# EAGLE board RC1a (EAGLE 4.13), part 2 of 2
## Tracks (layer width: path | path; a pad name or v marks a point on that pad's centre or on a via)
19GHZANT  (via drill 0.7, 3.2 pad 5.84)
  Top 0.305: 102.78,78.88 102.66,79.01 | 102.78,78.88 102.78,78.76 103.93,78.76 | 102.78,78.88 v101.64,78.88
  Top 2.54: v103.93,49.04 v103.93,56.4 v103.93,63.77 v103.93,72.28 103.93,78.76
  Bottom 2.54: v103.93,49.04 v103.93,56.4 v103.93,63.77 v103.93,72.28 103.93,78.12 103.67,78.88 v101.64,78.88
19GHZANT1  (via drill 0.7, 3.2 pad 6.45)
  Top 0.305: 155.98,78.9 155.86,79.02 | 155.98,78.9 155.98,78.77 156.87,78.64 | v154.84,78.9 155.98,78.9
  Top 2.54: v156.87,55.27 v156.87,63.78 v156.87,72.29 156.87,78.64
  Bottom 2.54: v156.87,55.27 v156.87,63.78 v156.87,72.29 156.87,78.9 v154.84,78.9
19GHZANT2  (via drill 0.7, 3.2 pad 6.45)
  Top 0.305: 48.29,79.53 48.16,79.66 | 48.29,79.53 48.29,79.4 49.43,79.4 | 48.29,79.53 v48.16,79.28
  Top 2.54: v49.43,50.45 v49.43,57.05 v49.43,64.42 v49.43,72.93 49.43,79.4
  Bottom 2.54: v49.43,50.45 v49.43,57.05 v49.43,64.42 v49.43,72.93 49.43,78.77 49.18,79.53 v48.16,79.28
800MHZANT  (via drill 0.7, 3.2 pad 5.84)
  Top 0.305: 56.56,79.01 57.19,79.64 v58.46,78.88
  Top 0.406: 56.43,73.8 56.18,73.55 56.56,73.17 v56.56,69.74
  Top 2.54: 56.43,21.99 v56.56,22.24 v56.56,31.77 v56.56,41.42 v56.56,51.45 v56.56,60.21 v56.56,69.74 56.56,79.01
  Bottom 2.54: v58.46,78.88 56.81,78.88 56.43,78.12 56.43,21.86
800MHZANT1  (via drill 0.7, 3.2 pad 6.45)
  Top 0.305: 109.76,79.02 110.39,79.66 v111.66,78.9
  Top 0.406: 109.63,73.82 109.38,73.56 109.76,73.18
  Top 2.54: 109.76,21.24 v109.76,21.36 v109.76,29.24 v109.76,37.75 109.76,42.19 | 109.76,42.57 v109.76,52.61 v109.76,61.12 v109.76,70.26 109.76,73.18 109.76,79.02 | 109.76,42.19 v109.76,45.11 109.76,42.57 | 109.76,42.19 109.76,42.57
  Bottom 2.54: v111.66,78.9 110.01,78.9 109.63,78.13 109.63,20.98
800MHZANT2  (via drill 0.7, 3.2 pad 6.45)
  Top 0.305: 2.82,79.66 3.46,80.29 v4.98,79.28
  Top 0.406: v2.7,74.45 2.44,74.2 2.82,73.82 2.82,70.39
  Top 2.54: 2.82,11.08 v2.82,11.33 v2.82,17.43 v2.82,24.29 v2.82,31.52 v2.82,39.65 v2.82,47.78 v2.82,56.8 v2.82,65.69 2.82,70.39 2.82,79.66
  Bottom 2.54: v4.98,79.28 3.08,79.53 2.7,78.77 2.82,10.95
+6V  (via drill 0.5, 0.6)
  Top 0.305: 196.88,30.89 v196.88,32.67 | 202.85,28.86 203.23,28.73 203.1,28.61 C56.1 | 203.1,25.43 203.23,25.56 203.1,25.66 C15.1 | 203.04,23.08 202.97,23.02 C54.1
  Top 0.406: 196.88,30.89 202.85,30.89 202.85,28.86 202.85,26.19 | 202.85,26.19 203.1,25.43 203.1,23.27 203.04,23.08 203.1,23.02 | 203.37,25.92 203.36,25.81 202.85,26.19 | C54.1 205.14,23.15 205.26,23.27 205.25,23.28 R8.2 208.3,23.28 208.31,23.27 208.4,23.36 C26.+ 208.55,20.24 208.56,20.98 208.55,20.97 D2.C 210.31,19.62 211.1,18.82 211.1,12.73 208.31,12.73 207.29,11.71 v207.29,8.92 | C14.1 184.31,20.48 | C14.1 | 183.78,19.7 183.78,19.95 C14.1
  Top 0.508: v190.64,13.1 188.37,15.9 185.55,15.9 183.78,17.67 183.78,19.7 | IC11.7 187.08,57.93 190.51,57.93 v190.51,51.96
  Top 0.61: C14.1 | C14.1 184.8,20.97 | C14.1 184.04,20.21
  Bottom 0.305: 190.64,51.58 190.64,51.83 190.53,51.95 | 190.53,51.95 v190.51,51.96 | 190.53,51.95 190.53,38.38 193.58,35.33 196.37,35.33 196.88,34.83 v196.88,32.67
  Bottom 0.406: v190.51,51.96 190.77,51.96 | 201.7,9.81 201.7,7.1 R19.1 201.6,6.61 201.58,6.63 201.83,6.89 | 201.7,9.81 201.96,10.19 195.1,10.19 194.47,10.95 | 194.47,10.95 194.47,12.47 193.83,13.11 191.9,13.11 v190.64,13.1 | 192.83,8.02 192.95,7.89 | 192.83,8.02 C37.1 | 192.95,7.89 IC8.8 | 192.95,7.89 193.07,7.78 | 192.83,8.02 194.47,9.65 194.47,10.95 | v207.29,8.92 207.29,9.05 205.26,9.05 204.12,10.19 202.09,10.19 201.7,9.81
+12V  (via drill 0.5)
  Top 0.305: IC12.3 186.87,49.17 v185.94,49.04
  Top 0.406: 186.7,32.95 D3.C 186.11,32.83 184.94,31.65 183.8,31.65 | 183.02,28.85 183.15,28.72 183.15,28.47 | 183.15,28.47 183.15,28.34 | 183.15,28.47 183.02,28.47 | C19.1 183.28,28.47 183.15,28.47 | 183.29,28.34 183.29,28.35 | C19.1 183.29,28.34 | 183.29,28.34 183.29,28.22 | v181.26,36.35 181.26,34.57 181.28,32.67 181.38,32.56 | C19.1 183.29,28.45 | 181.38,32.56 181.38,32.41 182.15,31.65 183.8,31.65 | C27.+ 181.38,33.11 181.38,32.56 | C19.1 183.42,28.35 183.42,31.27 183.8,31.65
  Top 0.61: IC4.4 189.88,33.55 189.16,32.83 D3.C
  Bottom 0.61: 185.19,49.56 168.18,49.56 168.18,51.21 161.57,51.21 161.57,39.53 163.94,39.53 IC13.3 163.94,39.73 163.86,39.65 163.86,37.62 165.13,36.35 v181.26,36.35
  Bottom 0.813: 185.19,49.56 185.81,48.94 v185.94,49.04
+24V  (via drill 0.5)
  Top 0.305: C18.1 167.8,21.5 167.67,21.63 | v167.41,23.02 167.67,23.12 R13.2 | 181.51,0.92 181.64,0.79 185.45,0.79
  Top 0.406: v188.1,12.85 184.56,9.18 | 172.89,1.29 167.41,6.89 v167.41,12.22 | R13.2 169.03,25.01 168.9,25.14 | C18.1 168.32,20.87 | 167.8,21.5 167.8,21.49 167.41,21.87 v167.41,23.02 | 167.8,21.5 | 168.9,25.14 166.58,27.46 164.29,27.46 C20.+ 164.24,27.51 | 164.24,27.51 164.24,27.33 | C55.1 164.24,30.26 164.24,27.51 | 168.9,25.14 168.81,25.05 168.81,26.65 D4.C
  Top 0.508: 172.89,1.29 173.26,0.92 181.51,0.92 | 185.45,0.79 187.73,0.79 187.73,4.09 184.56,7.27 184.56,9.18
  Bottom 0.305: IC9.8 194.79,13.42 192.81,14.89 188.1,14.89 188.37,15.4 188.61,15.63 C35.1
  Bottom 0.406: 188.1,14.89 v188.1,12.85 | v167.41,12.22 v167.41,23.02
CLK
  Bottom 0.254: 186.08,24.16 180.62,29.62 172.11,29.62 IC14.9
  Bottom 0.305: IC6.24 190.06,24.16 186.08,24.16
CP_IF  (via drill 0.5)
  Top 0.305: R40.2 183.15,55.01 183.15,52.34 182.51,51.71 182.53,37.37 178.72,37.37 | v178.72,33.68 178.72,37.37 | 178.72,37.37 178.72,36.1 C83.1
  Top 0.406: 183.15,55.01 183.53,55.39 v183.53,56.28
  Bottom 0.305: IC16.5 183.54,56.29 v183.53,56.28 | IC6.28 186.08,27.84 181.13,32.79 178.84,32.79 179.36,32.66 R41.1 178.84,32.67 178.72,32.67 v178.72,33.68
CP_RF  (via drill 0.5)
  Top 0.254: 184.93,53.23 184.93,56.66
  Top 0.305: v188.23,56.66 184.93,56.66 184.8,56.66 183.91,57.55 182.89,57.55 | 182.89,57.55 182.89,57.42 | 184.93,53.23 183.15,51.45 183.15,36.75 v183.8,36.1 | 182.89,57.55 R42.2
  Bottom 0.254: 190.53,30.79 189.26,32.06 189.26,34.19
  Bottom 0.305: IC16.13 189.42,58.24 188.23,57.04 v188.23,56.66 | IC6.23 191.07,23.05 190.78,22.76 189,22.76 188.26,22.78 R43.2 186.85,22.76 186.85,21.62 C84.1 | 189.26,34.19 187.35,36.1 v183.8,36.1
  Bottom 0.406: IC6.23 191.07,30.22 190.53,30.79
D+
  Top 0.305: U$6.3 83.16,7.95 83.61,7.51 83.61,2.43 82.46,1.29 76.37,1.29 76.15,1.51 IC2.15
D+1
  Top 0.305: U$1.2 135.56,7.88 136.05,7.39 136.05,4.22 133.34,1.52 131,1.52 130.33,2.19 129.31,2.19 IC3.16
D-
  Top 0.305: IC2.16 76.11,2.17 77.13,2.17 77.38,1.92 82.21,1.92 82.97,2.68 82.97,7.25 82.34,7.89 82.34,8.91 82.36,8.93 U$6.2
D-1
  Top 0.305: U$1.3 136.36,7.97 136.81,7.52 136.81,3.97 133.76,0.92 129.82,0.92 129.31,1.43 129.33,1.44 IC3.15
FB
  Top 0.305: IC5.8 174.27,17.68 172.62,17.68 | R14.2 171.07,17.68 172.62,17.68 | R13.1 172.62,22.41 172.62,17.68
GND  (via drill 0.6)
  Top 0.305: IC1.2 100.24,14.75 100.88,14.11 102.66,14.11 102.66,15.83 | 102.66,15.83 102.66,15.89 | IC1.4 102.66,15.83 | R2.1 66.34,3.89 66.78,3.89 66.84,4.21 66.84,8.4 66.34,8.91 66.34,11.32 66.97,11.95 70.27,11.95 | 70.27,11.95 C7.2 70.02,11.95 70.02,13.35 74.71,13.35 | 70.27,11.95 70.4,11.95 | 74.72,13.35 74.84,13.35 74.84,12.21 C6.2 74.71,13.35 | C1.- 80.15,13.35 74.72,13.35 | 74.72,13.35 74.71,13.35
  Top 0.406: R1.1 101.77,10.31 103.67,12.33 | 103.67,12.33 C3.2 | IC1.4 103.67,14.94 103.67,12.33 | C1.- 80.56,13.6
  Top 0.61: C1.- 80.31,13.6 80.31,12.33 v80.56,12.08 | 100.5,9.29 98.47,7.25 93.06,7.25 91.21,9.1 91.21,9.19 | R1.1 101.77,9.29 100.5,9.29 | 100.5,9.29 v99.36,10.43 | 91.21,9.19 91.21,9.29 | 91.21,9.19 J1.RING
  Bottom 0.61: v80.56,12.08 80.69,12.21 97.56,12.21 97.58,12.22 97.58,12.21 v99.36,10.43
GND1  (via drill 3.2 pad 6.45)
  Top 0.305: 123.22,13.36 127.91,13.36 | C10.2 123.22,11.96 123.22,13.36 | 127.91,13.36 C12.2 128.04,12.22 128.04,13.36 127.91,13.36 | 129.33,8.16 IC3.25 127.66,8.02 127.66,5.36 | 129.33,8.16 IC3.26 127.53,8.67 127.53,8.66 | 129.33,8.16 129.31,8.16 | 127.66,5.42 IC3.21 | 127.66,5.42 124.49,5.42 124.49,6.07 IC3.7 | IC3.18 127.66,3.47 127.66,5.36 | 127.66,5.36 127.66,5.42 | 127.53,8.66 127.54,8.66 | 127.28,11.21 127.28,8.66 127.53,8.66 | 139.22,13.36 123.22,13.36
  Top 0.406: U$1.5 137.95,9.08 137.95,9.68 139.22,10.95 139.22,13.36 139.22,16.34 C11.- | C12.2 127.28,11.21
  Top 0.813: JP1.4 111.53,17.68 113.95,15.27 C8.2 114.22,15.25 114.33,15.14 114.34,15.15 C9.2 117.17,25.23 119.54,27.59 131.35,27.59 134.39,24.54 BAT2.- 139.42,19.38 C11.-
  Top 1.27: v156.11,3.97 153.32,3.97 141,16.28 139.6,16.28 139.42,16.46 C11.-
GND2  (via drill 0.5, 0.6, 1.6, 2, 3.2 pad 5.84)
  Top 0.254: IC4.8 193.56,26.69 | 207.67,38.64 208.44,38.51 209.58,38.51
  Top 0.305: 176.7,38.27 v178.32,39.9 178.32,40.15 | IC4.8 193.69,26.69 | VCO2.P$1 171.46,39.77 | 191.05,33.57 191.15,33.67 | 191.05,33.57 IC4.3 191.16,33.59 | 191.05,33.57 191.02,33.55 | 195.34,39.64 VCO1.P$1 v195.09,39.77 | 181.88,44.21 181.62,44.47 181.62,41.17 | U$8.GND4 178.19,79.39 | v185.69,40.79 185.31,40.4 | 177.46,38.12 176.8,38.12 176.67,38.25 176.68,38.25 | 170.84,20.98 | 170.84,20.98 R14.1 | C18.2 170.84,20.5 170.84,20.98 | C28.2 176.56,15.4 176.56,12.56 177.54,11.59 | IC4.8 193.69,26.97 193.7,26.95 v193.58,26.83 | C14.2 184.31,23.27 184.43,23.14 v184.18,23.27 | IC4.1 193.7,32.16 v192.48,31.04 | 178.34,21.49 178.46,21.62 v178.21,21.62 | 208.31,38.76 207.67,38.64 207.8,35.74 JP4.6 | 176.68,38.25 176.69,38.26 | v174.65,33.18 174.65,36.1 | 174.65,36.1 174.65,38.26 176.68,38.25 | C15.2 205.26,25.93 205.26,28.47 C56.2 | C57.2 200.31,3.97 202.85,3.97 202.85,1.55 202.97,1.55 R32.2 | IC4.8 193.7,27.44 193.7,27.59 197.26,27.59 C58.2 | 174.65,36.1 C83.2
  Top 0.406: 193.82,27.55 IC4.8 193.71,27.45 193.82,27.45 | 191.15,33.67 191.28,33.8 | 171.21,39.64 171.21,39.77 VCO2.P$1 | IC10.2 174.38,5.23 172.48,5.23 171.72,5.99 171.72,6.75 171.84,7.26 | 171.84,7.26 171.78,7.32 | 171.78,7.32 171.85,7.38 | 171.75,11.2 171.84,7.26 | 171.72,12.72 171.75,11.2 | 171.72,12.72 169.05,15.39 C25.- 169.19,15.1 169.19,15.14 165.89,15.14 163.48,17.55 | v188.74,39.26 188.74,38.5 | 171.78,7.32 171.72,7.38 171.59,7.38 C21.2 | 182.89,23.26 C14.2 | 182.89,23.26 182.89,25.55 C19.2 183.54,25.68 183.67,25.68 | 182.91,23.4 182.91,17.17 183.54,16.54 v183.54,13.24 183.48,13.3 184.18,14.25 188.37,14.25 189.26,13.36 v189.26,11.08 | 182.91,23.4 182.91,23.65 | 182.89,23.26 183.04,23.37 182.91,23.4 | 171.75,11.2 171.86,11.2 | 177.54,11.59 C24.- 178.94,9.81 178.59,10.16 v178.59,11.33 | 171.72,12.72 171.73,12.73 v171.73,15.78 173.1,15.78 C16.2 173.51,16.19 173.51,16.16 175.67,16.16 C28.2 176.56,15.27 | IC5.4 180.42,21.49 178.34,21.49 178.08,21.75 | IC5.7 174.4,19.08 176.18,19.08 | 176.18,19.08 176.18,21.49 174.27,21.49 | 174.27,21.49 | 174.27,21.49 IC5.5 | 176.56,15.27 176.56,15.14 | 176.18,19.08 176.56,18.7 176.56,15.4 176.56,15.27 | 163.48,17.55 JP2.4 164.16,18.36 C20.- 164.05,20.6 163.99,20.6 163.99,22.51 161.83,24.67 161.83,31.02 163.35,32.54 165.64,32.54 | C18.2 167.9,17.55 163.48,17.55 | v193.43,10.56 193.58,10.56 193.58,15.26 195.52,15.26 195.72,15.39 195.72,15.64 195.75,15.16 R7.1 195.86,15.4 195.74,15.91 198.65,18.82 198.66,19.33 198.66,23.9 198.28,24.41 C58.2 | v177.69,68.09 177.44,67.96 177.45,67.97 Q5.2 | v209.45,3.84 209.32,3.84 207.03,1.54 R32.2 | v209.96,17.3 208.18,17.3 207.8,17.68 IC17.2
  Top 0.406: R9.1 201.46,23.66 v201.7,23.78 | v210.34,29.75 210.33,29.76 C26.- 208.93,28.49 208.94,28.73 208.96,25.82 C15.2 | C17.2 179.86,4.72 179.86,6 v179.23,6.63 | C55.2 167.54,32.54 165.64,32.54 | C27.- 176.05,32.95 176.05,32.79 175.8,33.05 174.65,33.05 v174.65,33.18 | IC4.3 191.15,34.94 191.67,35.46 193.45,35.46 193.7,35.21 193.7,33.56 IC4.1 | IC4.1 | 165.64,32.54 165.11,33.06 | C13.2 200.31,3.97
  Top 0.61: 183.15,23.39 C14.2 | 201.07,68.86 Q4.2 | 165.11,33.06 v165.11,38.12
  Top 1.27: Q4.2 196.88,68.86 | Q5.2 173.38,67.97
  Bottom 0.254: IC16.14 192.16,57.59 192.42,57.84 192.42,58.69 192.16,58.95 191.11,58.95 IC16.12 191.02,58.89 | v193.58,26.83 192.67,25.53 | 193.58,27.59 193.7,27.46 193.7,26.95 | 191.87,31.27 192.12,31.02 v192.48,31.04 | 210.09,25.17 209.98,24.84 | 201.86,24.84 201.7,24.67 v201.7,23.78
  Bottom 0.305: D6.A 178.32,40.15 v178.32,39.9 | U$8.GND4 178.07,80.54 v177.69,78 | v173.37,78.12 U$8.GND | U$9.GND4 201.82,79.65 201.94,79.77 200.93,77.74 | 183.27,60.6 C73.2 183.15,60.69 | C72.2 181.92,60.6 183.27,60.6 | C71.2 195.17,52.89 195.21,52.85 C70.2 196.61,52.89 196.61,52.6 | v183.02,80.16 183.27,80.79 183.4,75.97 | v192.42,78.63 190.39,77.23 191.02,76.6 C81.2 | 183.27,60.6 179.59,60.6 179.21,60.98 179.21,70.88 180.86,74.31 183.53,74.31 183.66,74.44 | 196.61,52.22 v196.61,52.47 196.61,52.6 | 196.61,56.28 C80.2 | 196.61,52.6 196.61,56.28 | 192.42,57.84 192.42,58.95 196.99,58.95 196.99,56.28 196.61,56.28 | 187.59,47.43 C76.2 | C77.2 187.59,48.75 187.59,47.43 | v185.69,40.79 185.94,41.42 IC15.2 185.94,45.9 C39.2 186.58,46.5 187.5,47.43 187.59,47.43 | IC16.2 183.87,54.34 183.27,53.74 182.13,53.74 C74.2 | C75.2 180.65,53.7 180.48,53.87 v179.97,53.87 | 178.36,18.72 178.46,18.82 IC14.1 178.46,19.46 178.34,19.33 178.19,19.48 177.3,19.48 177.19,19.59 IC14.2 177.19,19.46 177.45,19.71 177.45,20.73 | 173.38,19.46 173.38,17.3 171.61,15.52 | IC9.4 202.21,18.64 202.21,20.51 R20.1 201.7,21.52 v201.7,23.78 201.58,23.65 | C37.2 192.69,10.7 192.69,10.57 | 209.58,11.33 209.59,11.35 R22.1 | 209.58,11.33 209.47,11.44 | C23.2 209.44,16.79 209.45,16.79 209.47,16.78 | C23.2 209.44,16.55 209.45,16.54 209.47,16.56 | 209.83,18.32 209.58,18.32 209.44,18.18 | 177.45,20.73 176.81,21.36 173.89,21.36 173.38,20.86 173.38,19.46 | 173.38,19.46 IC14.5 | 191.54,20.98 191.54,21.24 192.69,22.38 192.69,23.97 | 191.54,20.98 191.54,20.76 C30.2 191.53,21 191.54,20.98 | 192.69,23.97 192.69,24.16 | 192.69,23.97 IC6.21 192.67,25.53
  Bottom 0.305: C35.2 189.01,18.56 190.53,17.05 192.81,17.05 192.81,19.71 191.54,20.98 | v184.18,23.27 184.14,22.67 R43.1 184.03,22.76 184.18,22.76 184.18,21.75 C84.2 | 191.87,31.27 IC6.3 | IC6.5 193.45,32.29 193.45,31.65 192.81,31.02 v192.48,31.04 191.93,30.38 191.93,29.11 193.58,27.59 | 193.7,26.83 v193.58,26.83 193.7,26.95 | 177.45,20.73 178.46,21.75 | 178.46,21.75 IC14.14 | 178.46,21.75 178.34,21.62 v178.21,21.62 | 209.83,38.26 209.7,38.39 | 209.58,11.33 209.71,11.2 210.47,11.2 | 210.47,15.27 210.21,15.27 210.21,15.28 | 210.21,15.28 C23.2 | 210.09,14.89 210.21,14.89 210.21,15.28 | 209.96,18.44 209.83,18.57 209.83,18.85 C22.2 | 210.59,21.75 210.47,21.75 209.73,21.75 R15.2 | 209.98,24.84 201.86,24.84 | R41.2 176.01,32.96 v174.65,33.18 | D5.A 193.03,6.63 188.62,6.63 188.37,6.89 188.37,10.7 188.62,10.95 189.26,10.95 v189.26,11.08
  Bottom 0.406: C38.2 v188.74,39.26 | 162.83,17.93 162.83,17.8 JP2.4 | 178.46,9.88 178.46,9.93 | 178.46,9.88 IC7.1 178.46,9.85 178.46,9.55 | 178.46,9.55 178.46,8.41 | 178.21,6.76 C29.2 178.46,7.24 | R11.1 178.21,4.47 178.21,6.76 | 178.21,6.76 178.21,6.89 177.96,6.63 v179.23,6.63 | C32.2 171.61,14.61 171.61,15.52 171.61,15.65 v171.73,15.78 | 178.46,7.24 178.46,7.14 | 178.46,7.24 178.46,9.55 | 178.46,9.55 178.46,9.88 | IC8.6 190.33,10.57 190.4,10.57 190.4,11.08 | 190.4,11.49 IC8.5 190.31,11.59 | 190.4,11.08 190.4,11.49 | IC8.4 184.22,12.47 v183.54,13.24 | 192.43,11.33 192.56,11.33 | 192.43,11.33 192.28,11.33 | C37.2 193.05,10.57 | 209.07,4.09 209.32,3.84 v209.45,3.84 | 210.47,25.3 210.09,25.17 | 210.34,25.3 210.34,24.92 | 210.34,24.92 210.34,25.17 | 210.09,25.17 210.34,24.92 | 210.09,25.17 210.47,24.79 210.47,25.68 | v178.59,11.33 178.46,11.2 178.46,9.55 | C37.2 192.69,10.82 192.69,11.49 | 190.4,11.49 192.69,11.49 | 192.43,11.33 192.43,11.2 | 192.69,11.49 192.43,11.49 192.43,11.33 | C37.2 192.94,10.82 192.94,10.56 v193.43,10.56 | v189.26,11.08 190.4,11.08 | 209.96,14.76 210.09,14.63 | 210.09,14.89 209.96,14.76 | 209.96,14.76 209.83,14.76 | R16.2 209.47,14.27 209.96,14.76 | 209.96,18.44 v209.96,17.3 | 210.47,29.62 v210.34,29.75
  Bottom 0.508: 162.83,17.8 162.71,17.8
  Bottom 0.813: 209.71,3.97 209.58,3.84 v209.45,3.84 207.16,1.54 197.52,1.54 194.47,4.6 194.34,4.6 194.67,4.93 D5.A
  Bottom 1.27: v209.45,3.84 209.83,5.11 210.47,5.74 210.47,11.2 210.47,15.27 210.47,17.17 209.83,18.32 209.96,18.44 210.47,18.95 210.47,21.75 210.47,24.79 210.47,25.3 210.34,25.3 210.47,25.68 210.47,29.62 210.47,37.62 209.83,38.26 209.83,39.27 206.53,39.4 206.53,39.28 v206.52,41.42
  other vias: 189.5,78.89 204.1,41.55 201.82,39.77 202.83,42.06 200.42,41.93 203.98,44.47 203.98,47.9 201.18,48.66 202.32,50.69 197.24,50.44 194.96,50.44 198.01,48.79 198.64,45.74 201.56,44.98 198.39,42.94 196.1,42.94 195.8,45.36 195.59,47.77 211.88,40.56 194.96,42.06 204.86,64.53 184.54,81.81 181.12,70.12 166.13,54.76 203.98,78 203.72,80.16 196.86,60.72 194.32,81.04 190.77,81.3 196.86,62.38 185.31,78.5 204.1,51.45 181.12,47.9 176.92,47.9 173.04,47.82 179.39,45.36 176.04,39.13 174.51,43.83 171.72,45.33 176.04,41.8 169.3,45.23 175.02,47.9 177.97,43.4 171.72,42.61 178.96,47.9 169.43,41.8 171.08,47.9 180.86,40.91 171.59,69.74 171.08,76.98 180.35,79.65 162.32,66.82 173.5,51.33 177.69,51.45 171.59,51.33 162.19,52.6 163.21,74.69 165.11,74.31 167.15,74.19 169.05,72.79 170.96,81.04 162.19,71.14 181.42,44.16 210.07,41.55 206.52,43.71 169.69,51.33 163.08,48.02 188.61,70 179.21,64.41 179.72,59.33 168.92,81.55 169.05,54.88 171.21,60.85 168.92,58.82 166.76,57.55 165.11,62.88 168.54,61.87 165.11,66.44 206.64,47.9 209.94,45.74 210.33,50.18 206.64,52.09 210.71,54.5 206.64,59.33 211.72,75.33 207.79,70.88 211.6,64.92 205.25,81.68 207.91,64.92 203.85,61.11 209.06,61.61 207.91,55.77 211.09,58.69 161.68,76.47 172.86,76.6 169.56,77.62 169.56,64.28 173.37,79.9 177.69,79.65 177.69,81.43 173.24,81.68 180.35,65.8 179.85,74.31 179.46,61.61 181.24,60.47 196.86,65.8 192.8,66.69 196.86,64.03 196.86,59.07 185.94,43.71 197.12,79.39 197.12,81.17 194.07,76.6 187.08,64.53 200.93,79.77 201.05,81.55 171.46,57.17 172.99,53.87 173.11,55.39 172.99,58.82 173.11,60.6 172.99,62.38 177.69,58.57 177.69,53.74 177.69,55.39 177.69,60.6 177.69,62.5 172.86,64.03 172.99,66.31 172.99,67.96 172.99,69.74 175.91,67.96 174.26,67.96 171.72,72.28 171.08,79.01 181.88,68.73 177.81,66.19 177.69,69.61 178.96,70.25 177.69,74.69 177.69,76.35 180.86,77.11 181.5,74.31 183.66,75.84 181.75,66.57 171.59,67.96 171.59,66.31 195.09,74.44 193.18,74.82 190.77,75.96 196.86,67.2 195.34,68.85 196.86,68.85 196.86,70.5 196.86,73.93 196.86,76.35 196.99,77.87 201.31,60.85 201.31,62.5 201.31,66.31 202.58,64.53 201.31,59.07 201.18,68.09 201.18,69.74 201.31,71.14 202.32,57.17 201.44,55.39 201.44,53.87 196.86,53.87 196.86,55.52 202.45,72.28 201.56,77.49 204.1,72.66 206.01,73.04 207.66,74.06 209.56,74.19 205.5,67.96 210.96,69.36 187.35,80.8 187.35,76.48 187.35,72.16 187.35,67.59 194.96,59.45 193.43,59.45 185.94,70 193.18,61.36 195.09,61.36 194.58,65.68 192.42,70.88 193.82,71.01 181.37,81.93 168.29,52.72 166.64,52.72 164.61,52.72 161.56,38.12 163.08,41.17 195.34,67.2 195.34,70.5 198.13,68.85 199.78,68.85 193.07,68.86 203.36,68.99 179.86,68.23 168.94,67.97 166.26,70.5 163.34,59.33 167.15,41.17 177.94,73.3 188.1,63.01 181.62,63.01 194.58,63.52 188.48,64.66
  pour Top (isolate 0.406): 160.8,37.86 160.92,82.06 173.51,82.06 173.51,52.61 177.45,52.61 177.45,82.07 197.39,82.45 197.39,52.99 200.94,52.99 200.94,82.06 213.12,82.06 212.99,37.99
  pour Bottom (isolate 0.406): 212.99,37.99 160.54,37.99 160.67,82.06 213.25,82.06
LBI  (via drill 0.6)
  Top 0.406: 195.97,11.83 196.08,11.93 R7.2 195.59,11.85 | 195.97,11.83 196.74,11.83 196.88,11.84 196.88,15.9 199.42,18.44 199.42,24.29 v199.67,24.54 | R6.1 195.1,9.71 195.1,10.96 195.97,11.83
  Bottom 0.305: v199.67,24.54 197.13,24.54 196.62,24.03 196.62,23.02 196.24,22.63 194.47,22.63 194.27,22.83 IC6.19
MISO
  Bottom 0.254: 197.39,25.43 198.15,25.43 198.28,25.56 202.21,25.56 202.34,25.43 208.82,25.43 209.32,25.94 209.32,32.03
  Bottom 0.305: 203.1,33.07 202.72,33.07 202.72,33.05 202.74,33.06 JP4.1 202.85,33.18 202.85,33.3 203.99,34.45 203.99,36.99 204.12,37.11 208.94,37.11 209.32,36.73 209.32,32.03 | IC6.16 197.37,25.43 197.39,25.43
N$1  (via drill 0.5, 0.6, 3.2 pad 5.84)
  Top 0.406: R1.2 104.56,9.41 v104.56,10.56 | IC1.5 102.66,21.16 102.66,21.22 v103.17,21.22 | 63.03,20.21 63.03,21.35 60.6,21.35 C4.2 60.51,21.33 60.49,21.35 59.73,21.35 56.81,18.43 JP3.4
  Top 0.508: 61.82,14.37 61.82,12.13 v60.87,11.19 | C5.2 61.97,6.16 62.14,5.98 v61.89,6.11
  Top 0.61: 72.56,21.48 72.59,21.48 BAT1.- 80.33,29.23 97.2,29.23 v97.2,16.4 | 72.56,21.48 72.56,20.21 63.03,20.21 C2.- 61.82,14.37 | 72.56,21.48 72.56,22.88
  Top 1.016: 102.91,3.7 102.66,3.7 | 102.91,3.7 v102.91,3.95 | R1.2 104.57,3.7 102.91,3.7
  Bottom 0.406: v104.56,10.56 104.56,16.14 104.31,16.65 103.17,18.18 v103.17,21.22
  Bottom 0.508: v60.87,11.19 60.87,7.13 v61.89,6.11
  Bottom 0.61: 104.31,16.65 104.44,16.4 v97.2,16.4
N$2  (via drill 0.6)
  Top 0.305: 76.13,8.14 IC2.25 74.46,7.97 74.46,7.27 74.46,5.35 | 76.13,8.14 IC2.26 | 76.13,8.14 76.11,8.14 | 74.46,5.41 IC2.21 | 74.46,5.41 71.29,5.41 71.29,6.06 IC2.7 | IC2.18 74.46,3.46 74.46,5.35 | 74.46,5.35 74.46,5.41 | J1.RING_SW 90.91,12.3 89.73,12.3 89.65,12.37 89.65,13.4 v89.61,13.4
  Top 0.406: U$6.5 84.76,10.19 86.26,11.69 90.64,11.69 90.87,11.92 | 91.18,12.03 91.18,11.92 90.87,11.92 | v73.88,7.31 74.46,7.27 | v89.61,13.4 89.65,13.44 89.69,13.44 89.69,13.1 90.87,11.92
  Bottom 0.406: v89.61,13.4 89.27,13.74 78.34,13.74 73.88,9.29 v73.88,7.31
N$3
  Top 0.305: R2.2 63.23,3.9 62.91,3.83 62.83,4.03 LED1.C
N$4
  Top 0.406: R3.1 103.67,16.75 103.67,17.67 103.42,17.92 101.64,17.92 101.64,15.89 101.57,15.89 IC1.3
N$5  (via drill 0.6)
  Top 0.406: 104.94,17.67 R3.2 105.2,18.94 | 105.2,18.94 R4.1 | Q2.B 101.62,25.8 v101.13,25.8 | v104.69,19.19 104.94,18.94 105.2,18.94
  Bottom 0.406: v101.13,25.8 104.69,22.24 v104.69,19.19
N$6
  Top 0.406: R5.2 101.9,23.1 101.9,23 104.33,23 R4.2 | R4.2 105.2,22.65 | R4.2 105.2,25.03 104.69,25.54 103.93,25.54 103.93,25.52 Q2.E
N$7  (via drill 0.6)
  Top 0.305: LED1.A 65.28,1.67 v66.46,1.67
  Top 0.406: D1.A 101.64,31.04 Q1.4 | D1.A 100.37,29.44 100.37,28.25 | D1.A 100.37,30.37 100.37,27.66 Q2.C
  Bottom 0.305: v66.46,1.67 67.1,2.05 97.58,2.05 98.34,2.81 98.34,7.51 99.36,8.52 105.83,8.52 105.83,36.46 101.64,37.1
  other vias: 97.96,43.2 97.96,41.42 97.96,39.51 97.96,37.61 99.86,43.2 101.9,43.2 105.32,43.2 103.55,43.2 105.32,41.54 105.32,39.64 105.32,37.61 101.64,37.61 100.88,41.8 102.78,41.8 99.61,37.61 103.67,37.61
  pour Top: 106.21,36.97 97.07,36.97 97.07,43.83 106.21,43.83
  pour Bottom: 106.21,43.83 97.07,43.83 97.07,36.21 106.21,36.21
N$8  (via drill 0.6, 3.2 pad 5.84)
  Top 0.406: D1.C 104.82,29.65 v104.82,27.7 | IC1.6 101.51,19.57 v100.63,18.68 | C2.+ 63.8,8.78 65.44,7.13 C5.1 | JP3.1 57.95,8.91 59.6,8.91
  Top 0.508: C2.+ 63.03,9.54 69,15.51 72.89,15.51
  Top 0.61: v95.42,27.32 88.69,21.13 BAT1.+ 88.59,21.48 88.31,21.48 82.34,15.51 72.89,15.51 | C2.+ 61.69,8.91 59.6,8.91 59.6,17.03 C4.1
  Top 1.016: JP3.1 56.94,9.92 56.94,4.71 v57.7,3.95
  Bottom 0.406: v100.63,18.68 98.34,20.97 98.34,27.32
  Bottom 0.61: v104.82,27.7 103.93,27.32 98.34,27.32 v95.42,27.32
N$9
  Top 0.406: IC1.7 100.12,20.4 100.12,24.78 98.47,24.78 98.47,33.42 99.36,33.42 99.36,33.59 Q1.1
N$10  (via drill 0.6)
  Top 0.305: IC2.1 67.77,9.96 v67.35,9.92
  Bottom 0.305: v67.35,9.92 64.99,9.95 62.3,12.64 56.76,12.64 | 56.7,12.64 56.76,12.64 | 56.76,12.64 JP3.2
N$11  (via drill 3.2 pad 6.45)
  Top 0.813: JP1.1 112.04,10.06 113.95,11.97 113.93,11.99 C8.1 113.95,12.47 117.12,12.47 117.12,12.41 C9.1 117.51,12.35 117.63,12.47 118.52,12.47 121.57,15.52 | 121.57,15.52 BAT2.+ | C11.+ 133,16.46 133,16.41 122.46,16.41 121.57,15.52
  Top 1.27: JP1.1 110.01,9.68 110.9,8.79 v110.9,3.97
N$12
  Top 0.305: C10.1 126.27,11.97 126.27,10.44 123.84,8.02 IC3.4 121.58,8.02 121.57,8.03 118.77,8.03 118.77,0.92 123.6,0.92 123.6,2.82 IC3.17
N$13  (via drill 0.6)
  Top 0.305: IC3.5 120.42,7.39 v120.04,6.76
  Bottom 0.305: v120.04,6.76 120.04,7.27 121.44,8.66 121.44,14.25 120.55,15.14 JP1.3
N$14
  Top 0.305: IC3.20 130.46,4.77 130.46,10.44 130.84,10.44 130.84,10.57 | C12.1 130.84,12.22 130.84,10.57 | 134.65,9.18 134.65,10.57 130.84,10.57
  Top 0.406: U$1.1 134.65,9.18
N$15  (via drill 0.6)
  Top 0.305: IC3.1 120.97,9.97 v120.17,9.93
  Bottom 0.305: v120.17,9.93 120.04,9.93 117.38,12.6 JP1.2
N$16
  Top 0.406: 206.13,11.83 206.02,11.71 L1.L2 206.01,11.58 204.68,12.91 | 204.68,12.91 204.48,13.1 | 204.68,12.91 204.63,12.86 204.4,13.08 IC17.1 206.85,16.73 207.5,16.74 D2.A | 204.68,12.91
N$17
  Top 0.305: C7.1 73.07,11.95 73.07,10.43 70.64,8.01 IC2.4 68.38,8.01 68.37,8.02 67.61,8.02 67.61,0.9 70.4,0.9 70.4,2.81 IC2.17
N$18
  Top 0.61: L2.L2 193.55,21.74 193.43,21.86 193.43,24.53 192.42,25.42 IC4.7 192.43,28.35 192.43,28.45 191.66,29.23 187.63,29.23 D3.A
N$19
  Bottom 0.406: Q3.B 172.95,6.38 172.62,6.05 172.62,4.85 173.13,4.35 174.91,4.35 174.91,4.42 | R10.1 180.5,11.92 180.5,5.62 179.48,4.6 179.48,3.08 178.72,2.31 174.91,2.31 174.91,4.42 | 174.91,4.42 R11.2
N$20
  Bottom 0.406: C32.1 172.21,11.2 172.11,11.2 172.11,9.26 Q3.C 171.61,8.75 171.61,8.41 173.13,8.41 174.15,7.39 174.15,5.87 177.19,5.87 177.19,12.47 | IC7.2 177.19,9.88 177.19,12.47 | 177.19,12.98 177.19,12.47 | 177.19,12.98 177.19,15.05 IC7.7 177.13,15.01 175.96,15.01 IC7.6 | 177.19,12.98 182.27,12.98 182.27,10.57 182.4,10.44 IC8.3
N$21
  Bottom 0.254: 184.31,16.54 184.81,16.54 184.81,13.62
  Bottom 0.305: IC14.3 175.92,17.81 179.61,17.81 | IC8.2 186.85,9.16 186.85,12.47 185.58,12.47 184.81,13.62 | IC14.13 177.19,26.32 177.7,26.83 179.1,26.83 179.61,26.32 179.61,17.81 | 179.61,17.81 181,17.81 182.27,16.54 184.31,16.54
  Bottom 0.406: IC8.1 184.94,7.9 184.94,9.11 IC8.2
N$22
  Bottom 0.254: IC14.12 175.92,28.73 180.37,28.73 181.38,27.46
  Bottom 0.305: IC14.12 175.92,25.17 | C33.1 191.27,18.46 191.29,18.44 189.89,19.71 187.35,19.71 185.96,18.32 182.91,18.32 181.38,19.84 181.38,27.46
N$23
  Top 0.406: IC5.3 180.52,20.35 177.07,20.35 177.07,26.06 176.56,26.57 174.65,26.57 174.65,26.69 L3.L2
  Top 0.61: L3.L2 174.91,26.71 174.91,26.44 172.78,26.44 D4.A
N$24
  Bottom 0.305: D5.C 199.85,4.22 201.58,4.22 201.7,4.09 201.78,4.09 R19.2 203.61,5.14 203.61,8.63 | 203.61,8.63 203.36,8.92 | 203.61,8.63 C36.2
N$25  (via drill 0.5)
  Top 0.406: R34.2 196.38,57.17 v195.99,57.56
  Bottom 0.406: 195.74,57.55 195.97,57.55 | 195.74,57.55 C79.1 | 195.74,57.55 195.74,57.56 v195.99,57.56
N$26
  Bottom 0.254: 169.7,19.71 169.7,30.89 181.26,30.89 185.96,26.19
  Bottom 0.305: IC14.7 169.93,19.48 169.7,19.71 | IC6.26 188.75,26.22 188.75,26.19 185.96,26.19
N$27
  Bottom 0.305: R17.2 204.13,17.95 202.59,16.54 201.32,16.54 200.94,16.92 200.94,18.57 200.93,18.59 IC9.3 200.69,18.86 200.69,22.25 200.56,22.38 198.02,22.38 197.01,21.36 195.35,21.36 195.35,18.44 195.09,18.43 C33.2
N$28
  Bottom 0.305: 198.53,21.24 198.49,21.27 R20.2 | R20.2 198.49,21.33 199.04,20.86 199.66,19.98 IC9.2 | R20.2 199.18,20.62 197.66,20.62 R18.1
N$29
  Bottom 0.305: 200.82,13.24 200.93,13.35 IC9.6 | 200.82,13.24 200.94,13.11 200.94,11.97 201.2,11.71 206.4,11.71 206.28,10.95 | 206.28,10.95 205.9,11.59 | 206.8,11.73 206.91,11.08 | R22.2 206.8,11.73 | 206.28,10.95 206.4,11.33 206.8,11.73 | 200.82,13.24 200.82,14.76 200.18,15.4 197.01,15.4 R21.1 | R21.1
N$30
  Bottom 0.305: IC14.4 174.65,17.3 174.91,17.05 180.75,17.05 182.78,15.01 183.04,15.01 183.15,15.13 C34.1
N$31
  Bottom 0.305: R90.2 198.15,8.38 198.15,8.41 200.46,8.41 C36.1
N$32
  Top 1.016: R28.1 183.79,70.63 183.54,71.9 183.54,71.92 C49.2 183.8,71.92 | L8.1 179.86,71.75 179.86,71.83 C47.2 181.51,71.71 | 181.51,71.71 181.51,71.96 C48.2 183.54,71.83 183.8,71.92 | 181.51,71.71 181.51,71.78 | 183.8,71.92 183.8,71.91
N$33
  Bottom 0.254: 186.2,15.64 187.15,16.54 189.44,16.54 190.4,15.65
  Bottom 0.305: 204.1,13.22 204.12,13.24 | R23.2 204.1,13.22 | 204.1,13.22 203.99,13.11 202.51,13.11 IC9.5 202.09,14.51 200.56,16.03 195.23,16.03 194.85,15.65 190.4,15.65 | 186.2,15.64 C34.2
N$34
  Bottom 0.305: 204.49,27.07 204.37,27.21 | 204.49,27.07 L5.1 204.37,27.08 204.12,27.21 203.86,27.08 198.95,27.08 198.91,27.04 IC6.14 | 203.74,26.7 203.7,27.04 204.49,27.07
N$35
  Bottom 0.305: L6.1 206.15,28.35 203.23,28.35 202.72,27.84 IC6.13
N$35R
  Top 0.406: C43.2 175.29,74.48 175.34,74.3 | 175.42,74.07 175.34,74.3 | 175.42,72.04 175.8,71.28 | 175.8,71.28 C60.1 | 175.34,74.3 175.39,74.3 175.42,74.32 175.22,74.52 C43'.2 | Q5.3 175.77,69.47 175.8,69.37 175.42,70.13 | 175.8,71.28 175.8,71.4 175.67,71.53 175.54,71.66 | 175.42,72.67 175.42,72.55 175.58,72.38 L8.2
  Top 1.27: 175.67,71.53 175.54,72 L8.2
  Top 2.184: 175.42,70.13 175.42,72.04 | 175.42,72.67 175.42,74.07
N$36
  Top 0.406: R26.2 199.15,53.89 199.16,54 | 199.15,51.7 199.04,51.59 | VCO1.P$10 199.15,51.7 | 199.16,53.24 199.16,51.97 199.15,51.7
  Top 2.184: 199.16,53.24 199.16,54
N$37
  Top 0.406: 185.81,60.6 IC11.8 185.69,60.98 185.69,64.69 184.94,65.43 R28.2
N$38
  Top 1.016: R27.1 190.53,70.89 190.53,72.3 C46.2 192.94,72.3 | 192.94,72.3 192.94,72.47 C44.2 195.1,72.47 195.1,72.43 | 192.94,72.3 192.81,72.42 | C45.2 195.1,72.34 195.1,72.43 | L7.1 195.1,72.43
N$39  (via drill 0.5)
  Top 0.61: 168.68,47.53 | VCO2.P$14 168.68,47.53 | 168.68,47.53 v168.05,47.53
  Bottom 0.61: C52.1 166.02,49.3 166.02,47.25 C53.1 | C53.1 167.03,47.53 v168.05,47.53 | L9.1 166.27,44.58 166.27,46.77 C53.1
N$40
  Bottom 0.61: 163.86,42.41 163.86,42.32 | IC13.4 163.86,42.41 | L9.2 163.86,43.69 163.86,42.41
N$41  (via drill 0.6)
  Top 0.305: IC2.5 72.05,7.38 v71.92,7.25
  Bottom 0.305: v71.92,7.25 71.95,11.29 68.2,15.04 56.89,15.04 56.89,15.05 JP3.3
N$42
  Top 0.406: R29.1 199.12,60.43 199.16,61.12 | C40.2 198.9,61.51 199.16,61.12 | 199.16,60.48 199.93,60.61 199.16,61.12
  Top 2.184: 199.16,61.12 199.16,60.48
N$43
  Top 0.406: 199.04,72.31 199.04,72.42 | L7.2 199.04,72.31 | 199.04,72.31 198.53,72.31 198.53,72.16 198.91,72.16 198.91,72.31 199.04,72.31 | 199.04,72.31 199.16,71.42 | C42.2 199.04,76.38 199.04,76.1 199.67,76.1 199.67,75.98 C42'.2 199.8,75.98 | 199.8,75.98 200.05,75.72 | C63.1 199.29,73.56 199.16,75.09 | 199.16,74.96 199.04,74.96 199.04,75.98 199.8,75.98
  Top 0.61: L7.2 198.9,72.43 198.86,71.86 Q4.3
  Top 2.184: 199.16,71.42 199.16,74.96 199.16,75.09
N$44
  Top 0.406: 187.09,47.64 L10.1 187.34,47.52 189.06,49.23 IC12.4
N$45
  Top 0.406: C51.1 C50.1 | C51.1 190.14,45.48 190.13,45.48 | L10.2 | C51.1 190.14,47.52 L10.2 | L10.2 190.39,47.26 VCO1.P$14
N$46
  Bottom 0.305: IC16.8 186.5,58.24 186.83,58.57 186.83,62.38 184.69,64.52 184.69,64.54 | 184.69,64.65 184.69,64.67 | 184.69,64.65 X1.X2 184.73,64.54 184.69,64.54 | 184.69,64.54 184.69,64.65 | C82.1 182.99,64.54 184.69,64.54
N$47
  Top 0.305: R30.2 175.54,54.54 175.54,53.75
  Top 2.184: VCO2.P$10 175.54,52.09 175.54,53.75
N$48
  Bottom 0.305: C80.1 193.31,56.28 193.3,56.29 IC16.16
N$49
  Top 0.406: 174.78,60.56 175.54,60.48 175.54,59.92 R31.1 | C41.2 175.54,61.78 175.54,60.86
  Top 2.184: 175.54,60.48 175.54,60.86
N$50  (via drill 0.5)
  Top 0.406: v179.97,55.77 179.86,55.91 179.86,57.04 R33.2
  Bottom 0.305: C78.1 180.77,55.35 180.35,55.77
  Bottom 0.406: v179.97,55.77 180.35,55.77 180.23,55.64
N$51
  Bottom 0.305: C78.2 182.64,55.14 182.51,55.01 182.53,54.99 IC16.3
N$52
  Bottom 0.305: IC16.15 192.39,56.94 193.01,57.55 C79.2
N$53
  Bottom 0.305: IC15.4 185.05,45.07 185.05,46.63 184.93,46.5 C39.1 184.8,46.5
N$54  (via drill 0.5)
  Top 0.305: R42.1 181.84,59.29 181.5,58.95 181.5,56.57 181.28,56.57 181.24,56.53 181.2,56.57 v181.15,56.57 | v181.15,56.57 181.19,56.53 | 181.15,56.62 181.12,56.66 | v181.15,56.57 181.15,56.62 | R40.1 181.54,56.24 181.15,56.62
  Bottom 0.305: R25.1 189.33,49.8 186.83,49.8 186.58,50.06 186.58,51.45 | IC16.6 186.68,56.94 186.83,56.79 186.83,55.77 186.77,55.71 | 186.77,55.71 186.83,55.64 186.83,52.09 186.7,52.22 | IC16.4 186.7,55.64 186.77,55.71 | 186.58,51.45 186.58,52.22 | 186.58,51.45 184.67,51.45 184.04,50.82 179.97,50.82 179.08,51.71 179.08,57.17 179.59,57.68 180.48,57.68 180.65,57.51 R24.2 180.65,57.26 181.24,56.66 v181.15,56.57
  Bottom 0.406: 189.37,47.43 189.37,47.52 | R36.2 189.37,45.83 189.37,47.43 | 189.37,47.43 C76.1 | 189.37,47.43 189.37,48.79 C77.1 189.37,48.83 189.37,50.86 | 189.37,50.86 189.37,50.95 | 189.37,50.86 R25.1 | 186.66,52.3 R35.2 | 186.58,52.22 186.66,52.3 | 186.66,52.3 186.66,52.25 186.7,52.22
N$55
  Bottom 0.406: Q3.E 169.5,7.85 169.45,12.47 169.45,14.25 168.92,14.78 R12.1
N$56
  Bottom 0.254: 168.94,18.82 168.94,31.52 181.51,31.52 185.96,27.08
  Bottom 0.305: R12.2 168.92,18.46 168.94,18.82 | IC6.27 188.74,27.08 185.96,27.08
N$57  (via drill 3.2 pad 5.84)
  Bottom 0.508: 174,1.16 174,1.19 165.26,9.93 163.35,9.93 JP2.1
  Bottom 0.61: 174,1.19 174.15,1.04 181.77,1.04 SW1.T
  Bottom 1.27: JP2.1 163.34,9.82 164.24,8.92 v164.24,3.84
N$58
  Top 0.406: R27.2 189.88,66.21 189.77,66.58 189.62,66.31 IC11.5
N$59
  Top 0.305: C41.1 175.29,64.37 175.42,64.04
  Top 0.406: 175.62,66.65 175.67,66.7 | 175.62,66.65 Q5.1 | 175.42,65.56 175.42,66.45 175.62,66.65 | C61.1 176.56,64.42 176.56,64.04 175.42,64.04 C61.1
  Top 2.184: 175.42,64.04 175.42,65.56
N$60
  Top 0.305: 200.17,1.54 R32.1 200.14,1.47 | 200.14,1.47 200.18,1.43 | LED2.C 200.06,1.54 200.14,1.47
N$61
  Top 0.406: C40.1 199.16,63.35 199.16,63.91 | 199.16,66.45 199.29,64.8 199.29,64.54 C62.1
  Top 0.61: Q4.1 199.37,66.65 199.16,66.45
  Top 2.184: 199.16,63.91 199.16,66.45
N$62  (via drill 0.5)
  Top 0.305: v184.16,48.41 184.16,51.45 185.81,53.1 IC11.1
  Bottom 0.305: v184.16,48.41 183.4,48.41 182.91,47.91 182.91,37.24 | 182.91,37.24 167.92,37.24 165.89,39.27 165.89,39.94 | 182.91,37.24 184.18,37.24 184.43,36.99 187.86,36.99 190.27,34.57 IC6.1 | IC6.1 190.27,32.29 | IC6.1 | 165.89,39.94 165.89,40.16 | 165.89,39.94 IC13.1
N$63  (via drill 0.5)
  Top 0.254: v194.97,30.76 194.97,31.91 197.26,34.45 204.37,34.45
  Top 0.305: JP4.3 205.26,33.2 205.26,33.56 204.37,34.45
  Bottom 0.254: IC6.17 195.87,24.92 194.97,25.81 v194.97,30.76
N$64
  Bottom 0.254: IC6.15 200.82,26.19 202.97,26.19 203.36,26.06 208.69,26.06 208.69,29.87 207.55,31.02
  Bottom 0.305: 207.55,31.02 206.53,32.03 206.53,34.32 205.26,35.59 205.26,35.72 205.27,35.72 JP4.4
N$65  (via drill 0.5)
  Top 0.254: 193.44,1.54 LED2.A 194.2,1.54 194.08,1.43 193.32,1.55 192.56,0.79 188.62,0.79 188.62,4.85 186.34,7.14 186.34,8.79 186.85,9.3 190.66,9.3 191.67,10.32 191.67,15.78 193.2,17.43 194.97,17.43 195.48,17.94 196.24,18.82
  Top 0.305: v195.86,26.44 196.24,26.44 196.24,18.82
  Bottom 0.305: IC6.11 195.86,29.44 v195.86,26.44
N$664  (via drill 0.5)
  Top 0.254: 187.53,51.13 186.01,51.13 185.07,50.19 185.07,47.4 184.18,46.51 184.18,37.87 v189.51,37.87
  Top 0.305: 187.53,51.13 IC12.1 | IC11.4 189.62,53.23 187.53,51.13 | 187.53,51.13 188.24,51.84
  Bottom 0.254: v189.51,37.87 189.89,37.87 193.32,34.45 194.97,34.45 195.86,33.43 195.86,32.67 195.87,32.66 IC6.8
N$666
  Bottom 0.305: IC16.7 187,57.59 188.1,58.69 188.1,60.34 189.77,62 190.53,62 190.66,61.88 190.75,61.97 X1.X1 192.02,61.97 192.69,62.64 193.2,62.64 193.21,62.65 C81.1
N$10077
  Bottom 0.305: IC16.1 185.05,53.67 185.05,52.3 | C75.1 182.09,52 182.13,51.96 C74.1 183.44,52 183.78,52.34 184.8,52.34 184.93,52.47 R35.1
  Bottom 0.406: 185.05,52.3 185.05,52.22 184.96,52.3 R35.1
PLL_CLK
  Bottom 0.305: IC16.19 189.84,54.34 189.62,54.12 189.62,53.23 190.01,52.85 191.02,52.85 191.53,52.34 191.53,50.84 192.56,49.81 192.55,37.23 193.58,36.22 196.62,36.22 197.89,34.95 197.89,31.02 197.39,31.02 IC6.9
PLL_DATA
  Bottom 0.305: IC16.20 191.2,53.69 192.16,52.72 192.16,51.1 193.2,50.07 193.18,37.48 193.93,36.86 197.39,36.86 198.78,35.33 198.78,30.64 198.36,30.25 IC6.10
PLL_LE
  Bottom 0.305: 191.28,55.01 191.25,54.99 | 191.28,55.01 192.04,55.01 192.8,54.25 192.8,51.48 192.81,51.46 193.94,50.44 193.94,37.74 194.31,37.49 197.89,37.49 199.55,35.59 199.55,30.64 200.18,30 200.18,28.98 199.8,28.6 197.39,28.6 197.36,28.63 IC6.12 | 191.28,55.01 191.15,55.01 191.13,54.99 IC16.18
RESET  (via drill 0.5)
  Top 0.254: 191.54,37.87 206.53,37.87 206.53,34.45
  Top 0.305: v184.56,33.18 184.81,33.43 184.81,34.95 187.99,34.95 190.91,37.87 191.54,37.87 | JP4.5 207.93,33.18 | JP4.5 | 206.53,34.45 207.8,33.18 JP4.5
  Bottom 0.305: IC6.29 186.17,28.64 184.56,30.25 v184.56,33.18
RF_OUT
  Top 0.305: U$8.COND 175.53,81.04
  Top 1.27: U$8.COND 175.54,81.68 175.54,77.07 C43.1
RF_OUT1
  Top 0.406: 199.16,80.03 199.16,80.04 | 199.16,80.03 U$9.COND | C42.1 199.16,78.08 199.16,80.03
RX
  Bottom 0.305: JP2.2 163.34,12.59 165.11,12.59 165.5,12.6 166.53,13.62 166.53,30.64 170.46,34.57 185.58,34.57 185.58,31.02 187.15,29.44 IC6.30
SDI
  Bottom 0.254: 185.81,25.44 181,30.25 170.72,30.25 170.72,25.56
  Bottom 0.305: IC6.25 185.81,25.44 | IC14.8 170.84,25.43 170.72,25.56
SENSE
  Top 0.406: IC17.3 204.4,19.74 205.13,20.48 | R9.2 202.89,20.44 202.98,20.35 C54.2 204.62,20.35 204.63,20.35 205.01,20.35 205.13,20.48 | 205.13,20.48 205.14,20.47 R8.1
STRIPLINE1  (via drill 3.2 pad 5.84)
  Top 0.406: C42'.1 202.34,75.22 202.34,75.21
  Top 2.184: v208.8,78.76 v208.8,78.75 205.73,75.68 204.6,75.21 202.34,75.21
STRIPLINE2  (via drill 3.2 pad 5.84)
  Top 0.406: C43'.1 172.49,74.52 172.49,74.58
  Top 1.016: 168.86,76.09 168.1,76.39 v165.62,78.76
  Top 2.184: v165.62,78.76 165.77,78.76 169.51,75.03 170.59,74.58 172.49,74.58
TX
  Bottom 0.305: IC6.31 187.62,30.24 186.21,31.52 186.21,35.21 170.21,35.21 165.64,30.89 165.64,15.01 163.47,15 JP2.3 163.35,14.99 163.35,14.89
VCC  (via drill 0.6)
  Top 0.305: 81.45,10.43 77.64,10.43 | 77.64,10.43 77.26,10.43 77.26,4.76 77.26,4.75 | 77.64,10.43 77.64,12.03 | 77.64,12.03 77.64,12.2 | 77.26,4.75 77.27,4.75 | IC2.20 77.26,4.75 | 81.45,9.29 81.46,9.29 81.46,9.16 U$6.1 | 77.64,12.03 77.5,12.03 77.5,11.84 C6.1
  Top 0.406: 98.91,19.95 98.85,19.95 98.85,22.9 R5.1 | 98.91,19.95 IC1.8 | C3.1 100.88,12.46 100.88,13.1 100.37,13.6 98.97,13.6 98.97,14.93 IC1.1 arc90 98.91,15.89 98.85,15.89 98.85,19.89 arc-90 98.91,19.95 | 81.38,10.49 81.45,10.43 81.45,9.29 81.45,9.17 | 81.38,10.49 81.19,10.43 | C1.+ 84.28,12.08 82.21,12.08 81.45,11.32 81.45,10.56 81.38,10.49 | J1.TIP 96.55,12.06 96.55,14.66 96.51,14.7
  Top 0.508: Q1.3 104.03,33.54 v104.82,33.54
  Top 0.61: C1.+ 85.8,14.93 90.95,14.93 | 98.97,14.93 96.51,14.93 | 96.51,14.93 90.95,14.93 | 96.51,14.93 96.51,14.7 96.57,14.7 | 90.95,14.93 90.95,14.77 91.06,14.89 v91.06,15
  Bottom 0.508: v104.82,33.54 101.39,30.11 93.39,30.11 91.23,27.96
  Bottom 0.61: 91.23,27.96 91.23,15.4 v91.06,15
VCC1  (via drill 0.5, 0.6)
  Top 0.254: JP4.2 196.25,35.73 196.12,35.84 195.61,36.22
  Top 0.305: 174.38,9.67 174.51,9.8 173.5,9.8 v173.38,9.68 | C24.+ 174.15,10.06 | C24.+ | 174.02,13.11 174.15,12.98 C24.+ | 174.02,13.11 173.89,13.24 | 173.89,12.98 | 174.02,13.11 173.89,12.98 | C16.1 173.89,13.24 173.89,12.98 | 195.61,36.22 190.79,36.23 v190.4,35.84 | 195.23,16.67 197.39,18.7 197.39,23.4 v197.64,23.4
  Top 0.406: IC10.5 173.62,6.71 173.62,8.03 176.81,8.03 | 175.15,9.67 175.4,9.67 | 175.15,9.67 175.15,9.8 175.54,9.8 175.61,9.87 | 175.61,9.87 175.65,9.91 | 175.15,9.67 175.02,9.8 174.51,9.8 174.26,9.8 C24.+ | C17.1 176.94,8.03 | 176.81,8.03 176.94,8.03 | v181.51,14.13 181.51,8.79 181.26,8.54 | 175.61,9.87 175.67,9.81 175.67,9.3 176.94,8.03 | 181.26,8.54 180.75,8.03 176.81,8.03 | 195.23,16.67 193.45,16.67 192.43,15.52 192.43,9.68 190.4,7.65 v187.35,7.65 | v181.51,8.54 181.26,8.54
  Bottom 0.254: 195.07,24.83 194.47,25.43 194.47,27.71 192.94,29.24 192.94,30.25 194.21,31.52 194.21,32.54 IC6.6 | 194.85,21.87 194.97,22 196.62,22 197.51,22.89 v197.64,23.4
  Bottom 0.305: 187.21,39.52 184.54,39.52 184.42,39.64 184.42,42.06 184.93,42.56 185.05,42.44 185.02,42.44 IC15.3 | C31.1 187.3,38.08 187.21,37.99 | 174.65,25.17 IC14.11 174.65,25.43 174.51,25.28 IC14.10 | IC14.10 173.38,22.89 172.11,21.62 172.11,19.59 | 172.11,19.33 IC14.6 172.11,19.59 | IC7.8 178.51,15.06 | 172.11,19.59 172.11,18.06 170.59,16.54 | IC7.4 174.64,9.44 174.65,9.43 174.4,9.68 v173.38,9.68 | 180.26,14.39 180.24,14.38 | 180.26,14.39 R10.2 | v181.51,14.13 180.62,14.76 180.26,14.39 | 173.26,25.17 173.36,25.28 IC14.10 | 170.34,16.28 170.21,16.41 | 195.1,23.9 IC6.18 | IC6.18 195.1,23.92 | 195.07,24.03 194.97,24.03 | 195.07,24.03 IC6.18 | 195.07,24.03 195.1,24.03 | 189.44,36.4 191.27,34.57 191.29,33.81 192.69,33.81 | 189.44,36.4 189.39,36.48 188.13,37.74 187.21,37.74 | IC6.4 192.69,32.54 192.69,33.81 | IC6.6 194.27,33.81 192.69,33.81 | 195.07,24.83 195.07,24.03 | 190.45,36.27 190.4,36.1 | 189.44,36.4 190.45,36.27 | 190.45,36.27 v190.4,35.84 | 194.47,25.43 194.08,25.43 193.47,24.81 IC6.20 193.47,21.73 194.08,21.11 194.08,21.1 C30.1 194.59,21.01 194.59,21.62 194.85,21.87
  Bottom 0.406: IC15.1 187.21,42.09 187.21,39.52 187.21,37.99 187.21,37.74 | R10.2 180.5,14.54 180.5,14.51 179.01,14.51 IC7.8 178.46,15.06 | C29.1 175.92,7.26 175.42,7.14 175.53,7.39 174.65,8.92 174.65,9.43 174.65,9.85 IC7.4 174.65,9.88 174.65,12.6 170.34,12.6 170.34,16.28 172.11,18.06 | v187.35,7.65 186.72,7.01 182.15,7.01 181.51,7.65 v181.51,8.54
VCC2
  Bottom 0.305: 194.11,54.59 C71.1 193.82,54.63 | 194.11,54.59 C70.1 | R25.2 187.59,50.86 187.59,51.2 188.99,52.6 188.99,55.14 189.5,55.64 IC16.17 192.29,55.64 193.18,54.76 193.94,54.76 193.82,54.63 | 194.11,54.59 193.85,54.59 193.82,54.63
VCC3
  Bottom 0.305: 182,58.82 183.24,58.82 C73.1 183.27,58.82 | 182,58.82 181.88,58.82 C72.1 181.97,58.86 182,58.82 | R24.1 182.35,58.6 182.22,58.6 182,58.82 | 183.27,58.82 183.15,58.69 | IC16.9 183.34,58.89 183.27,58.82
VCO1_DCADJ
  Bottom 0.305: C23.1 206.67,16.17 206.04,16.05 R23.1 | 206.64,14.27 R16.1 | 206.64,14.27 C23.1 | 206.64,14.27 206.66,14.25 | L6.2 207.4,23.79 208.18,23.02 208.18,16.41 207.67,15.9 206.91,15.9 206.77,16.05 C23.1
VCO1_OUT
  Top 0.406: R26.1 199.28,57.04 199.16,56.8 | R29.2 199.15,58.31 199.16,58.32 199.16,57.56 | R34.1 198.77,57.17 199.16,57.56 | R37.1 199.8,57.18 199.67,57.05 199.16,57.56
  Top 2.184: 199.16,57.56 199.16,56.8
VCO1_TUNE  (via drill 0.5, 0.6)
  Top 0.305: v208.69,9.68 208.69,11.46 212.12,11.46 212.12,30.51 211.61,30.89 v205.26,30.89
  Top 0.406: 197.63,39.64 VCO1.P$2 197.75,39.39 v198.39,39.39 198.26,39.26
  Bottom 0.254: D7.C 198.64,38.88 v198.39,39.39
  Bottom 0.305: R21.2 196.38,11.83 196.5,11.71 198.74,11.67 199.55,12.47 199.55,13.36 199.6,13.42 IC9.7 199.66,12.36 201.07,10.95 204.5,10.95 205.51,9.93 208.69,9.93 v208.69,9.68 | v205.26,30.89 200.69,30.89
  Bottom 0.406: v198.39,39.39 198.13,39.64 | 198.64,38.88 198.28,38.51 198.28,38.13 200.69,35.72 200.69,30.89
VCO2_DCADJ
  Bottom 0.305: C22.1 206.67,20.34 206.62,20.39 R15.1 206.62,22.17 206.66,22.13 205.91,21.37 R17.1 204.13,21.5 204.36,21.74 L5.2
VCO2_OUT
  Top 0.305: R30.1 175.54,56.24 175.54,56.8 | 175.29,57.81 175.54,57.18 | R38.1 175.29,57.43 175.54,57.43 175.54,57.3 R33.1
  Top 0.406: 175.29,57.81 175.42,57.81 175.42,58.22 R31.2
  Top 2.184: 175.54,56.8 175.54,57.18 175.54,57.43
VCO2_TUNE  (via drill 0.6)
  Top 0.305: 174.14,39.64 174.15,39.65 | 174.14,39.64 v174,39.64 | 174.14,39.64 174.02,39.53 174.02,36.48 173.51,35.97 173.51,31.65 173.76,31.4 177.07,31.4 v177.07,27.71
  Top 0.406: VCO2.P$2 174,39.77 v174,39.64
  Bottom 0.254: 191.04,16.41 190.35,16.41 189.66,17.05 186.21,17.05 185.83,17.43
  Bottom 0.305: 198.4,18.32 198.39,18.33 IC9.1 198.39,18.59 198.4,18.57 197.61,17.77 R18.2 195.83,17.52 194.72,16.41 191.04,16.41 | v174,39.64 174.15,39.5 | 185.83,17.43 182.65,17.43 180.5,19.59 180.5,26.57 | 180.5,26.57 180.5,26.7 | v177.07,27.71 179.99,27.71 180.5,27.21 180.5,26.57
  Bottom 0.406: D6.C 174,39.98 v174,39.64
VIN  (via drill 0.6)
  Top 0.305: IC5.2 180.51,19.06 180.5,19.08 181.51,19.08 182.02,19.59 182.02,23.52 181.64,23.9 181.64,26.95 184.81,26.95 184.88,26.89 188.22,23.54 188.22,23.27 L2.L1 | 194.72,4.73 | C57.1 194.72,4.73 | 194.72,4.73 194.72,7.14 | 192.31,29.87 191.67,30.25 190.91,31.02
  Top 0.406: 169.05,8.78 168.92,6.62 173.11,2.43 173.37,2.43 | 169.05,8.78 C25.+ 169.05,10.56 | 173.37,2.43 174.89,2.43 175.33,2.87 | 175.33,2.87 175.33,2.43 | 175.33,2.87 IC10.3 | 173.37,2.43 173.37,2.56 173.43,2.62 IC10.1 | C21.1 169.05,7.51 169.05,8.78 | IC17.4 201.8,16.82 201.83,16.79 201.8,16.76 IC17.5 201.8,13.33 201.18,12.71 201.18,12.59 200.41,11.82 L1.L1 199.52,10.68 198.51,8.02 197.39,6.89 197.39,6.25 C13.1 196.88,6.76 194.99,6.76 | IC5.1 180.53,17.65 180.5,17.68 180.53,17.72 IC5.1 | IC5.1 IC5.2 | IC5.1 180.42,17.68 180.37,17.68 180.37,16.31 C28.1 179.58,15.52 182.53,15.52 182.53,6 | 188.22,23.27 188.37,23.78 191.15,26.56 IC4.6 | IC4.2 192.42,32.53 190.91,31.02 190.27,30.38 185.58,30.38 184.94,29.75 184.94,26.95 184.88,26.89 | L3.L1 180.37,26.86 180.37,26.95 181.64,26.95 | C58.1 196.75,29.37 192.94,29.37 192.31,29.87 | 194.99,6.76 194.97,6.76 194.85,7.14 194.72,7.14 | 194.99,6.76 R6.2
  Top 0.508: 182.53,6 181.26,4.73 181.26,3.08 180.37,2.31 175.89,2.31 175.77,2.44 | 194.72,4.73 194.21,5.24 192.18,5.24 190.78,3.84 190.78,2.95 SW1.P
  Top 0.61: C25.+ 169.3,10.94 | C57.1 194.72,4.73 | 175.77,2.44 175.33,2.87 | 182.53,6 183.92,6 186.34,3.58 v186.34,2.82
  Bottom 0.61: SW1.P v186.34,2.82
VPP
  Bottom 0.305: IC15.5 186.96,45.07 186.96,45.1
  Bottom 0.406: 187.48,45.21 187.38,45.1 186.96,45.1 186.86,45.1 | 187.48,45.21 R36.1 | 187.48,45.21 187.47,45.23 187.47,44.73 C38.1
(copper drawn outside any net)
  shapes: Top area x1

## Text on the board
Bottom: www.ladyada.net | Wave Bubble | Wave Bubble | www.ladyada.net | Wave Bubble | www.ladyada.net | v1.0b
bPlace: Good. | Can you hear | me now?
